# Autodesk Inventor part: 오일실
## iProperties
IsCustomPart: 1
Created: 2009-02
Part Number: 오일실
Material: 고무
Description: 오일-실
Document SubType Name: Modeling
Standard: KS B 2804
Designer: SeoGD™[esajin.kr]
Standards Organization: KS
Language: ko-KR
Size Designation: D - 15 25 7
Categories: <MemberInstance><Categories><Category DisplayName="샤프트 부품" InternalName="7f7aeb1f-a693-4053-b835-cee3144e0d98" Mnemonic="SHFT"><Category DisplayName="실링" Intern
Density: 0.93 g/cm^3
Author: SeoGD™[esajin.kr]
